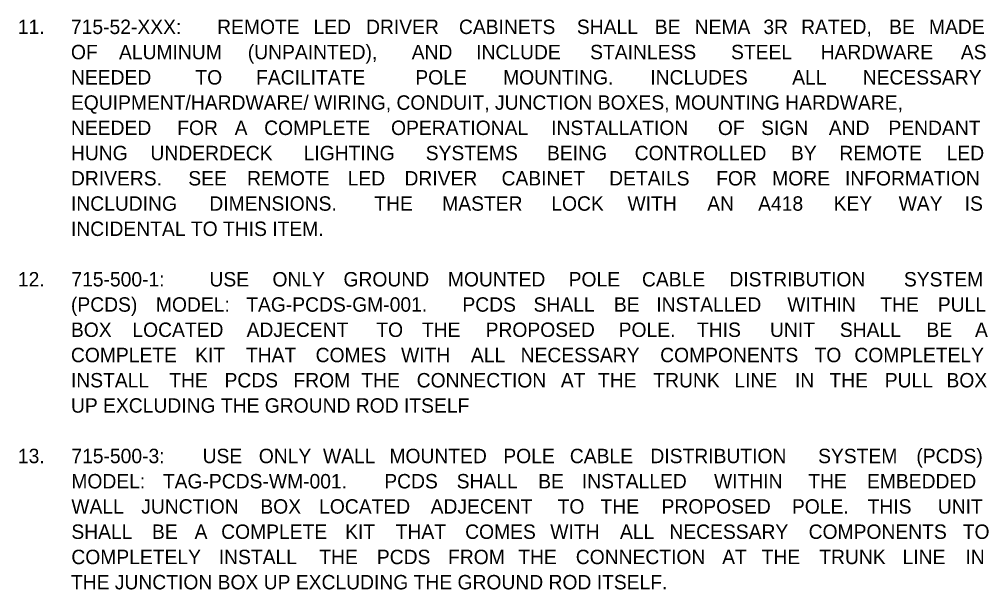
# Model space of a CAD drawing. Extents: x -55 to 2471539, y -90 to 3608906.
# Drawn here: x 543.9 to 1014.7, y 3095.6 to 3372.3 of the extents above; entities that cross this region are included whole.
import ezdxf

# ---------------------------------------------------------------- set-up
doc = ezdxf.new("R2010")
doc.units = 0
doc.layers.add('XSCell', color=7, linetype='Continuous')

msp = doc.modelspace()

# ---------------------------------------------------------------- texts
at = {"layer": 'XSCell'}
for s, p in [('11.', (543.22, 3365.2)), ('715-52-XXX: ', (568.97, 3365.2)), ('REMOTE ', (639.98, 3365.2)), ('LED ', (686.77, 3365.2)), ('DRIVER ', (712.3, 3365.2)), ('CABINETS ', (757.41, 3365.2)), ('SHALL ', (814.68, 3365.2)), ('BE ', (852.51, 3365.2)), ('NEMA ', (871.89, 3365.2)), ('3R ', (905.27, 3365.2)), ('RATED, ', (923.6, 3365.2)), ('BE ', (966.31, 3365.2)), ('MADE ', (985.69, 3365.2)), ('OF ', (568.97, 3352.95)), ('ALUMINUM ', (592.31, 3352.95)), ('(UNPAINTED), ', (654.86, 3352.95)), ('AND ', (734.47, 3352.95)), ('INCLUDE ', (765.76, 3352.95)), ('STAINLESS ', (821.12, 3352.95)), ('STEEL ', (889.55, 3352.95)), ('HARDWARE ', (933.07, 3352.95)), ('AS ', (1001.15, 3352.95)), ('NEEDED ', (568.97, 3340.7)), ('TO ', (629.41, 3340.7)), ('FACILITATE ', (658.89, 3340.7)), ('POLE ', (736.22, 3340.7)), ('MOUNTING. ', (778.86, 3340.7)), ('INCLUDES ', (850.34, 3340.7)), ('ALL ', (919.26, 3340.7)), ('NECESSARY ', (953.5, 3340.7)), ('EQUIPMENT/HARDWARE/ WIRING, CONDUIT, JUNCTION BOXES, MOUNTING HARDWARE, ', (568.97, 3328.45)), ('NEEDED ', (568.97, 3316.2)), ('FOR ', (620.6, 3316.2)), ('A ', (648.48, 3316.2)), ('COMPLETE ', (662.81, 3316.2)), ('OPERATIONAL ', (724.44, 3316.2)), ('INSTALLATION ', (802.19, 3316.2)), ('OF ', (883.17, 3316.2)), ('SIGN ', (904.17, 3316.2)), ('AND ', (937.04, 3316.2)), ('PENDANT ', (966, 3316.2)), ('HUNG ', (568.97, 3303.95)), ('UNDERDECK ', (607.59, 3303.95)), ('LIGHTING ', (681.96, 3303.95)), ('SYSTEMS ', (741.27, 3303.95)), ('BEING ', (800.17, 3303.95)), ('CONTROLLED ', (842.75, 3303.95)), ('BY ', (918.66, 3303.95)), ('REMOTE ', (942.16, 3303.95)), ('LED ', (994.28, 3303.95)), ('DRIVERS. ', (568.97, 3291.7)), ('SEE ', (625.96, 3291.7)), ('REMOTE ', (654.53, 3291.7)), ('LED ', (703.36, 3291.7)), ('DRIVER ', (730.96, 3291.7)), ('CABINET ', (778.11, 3291.7)), ('DETAILS ', (830.37, 3291.7)), ('FOR ', (882.35, 3291.7)), ('MORE ', (909.54, 3291.7)), ('INFORMATION ', (944.87, 3291.7)), ('INCLUDING ', (568.97, 3279.45)), ('DIMENSIONS. ', (636.19, 3279.45)), ('THE ', (716.33, 3279.45)), ('MASTER ', (749.29, 3279.45)), ('LOCK ', (802.27, 3279.45)), ('WITH ', (839.28, 3279.45)), ('AN ', (877.99, 3279.45)), ('A418 ', (902.72, 3279.45)), ('KEY ', (939.37, 3279.45)), ('WAY ', (970.96, 3279.45)), ('IS ', (1003.04, 3279.45)), ('INCIDENTAL TO THIS ITEM.', (568.97, 3267.2)), ('12.', (543.22, 3242.7)), ('715-500-1: ', (569.17, 3242.7)), ('USE ', (636.23, 3242.7)), ('ONLY ', (666.85, 3242.7)), ('GROUND ', (701.34, 3242.7)), ('MOUNTED ', (752.04, 3242.7)), ('POLE ', (810.68, 3242.7)), ('CABLE ', (846.3, 3242.7)), ('DISTRIBUTION ', (888.74, 3242.7)), ('SYSTEM ', (973.52, 3242.7)), ('(PCDS) ', (568.97, 3230.45)), ('MODEL: ', (610.23, 3230.45)), ('TAG-PCDS-GM-001. ', (654.09, 3230.45)), ('PCDS ', (759.09, 3230.45)), ('SHALL ', (793.65, 3230.45)), ('BE ', (832.67, 3230.45)), ('INSTALLED ', (853.25, 3230.45)), ('WITHIN ', (916.87, 3230.45)), ('THE ', (962.03, 3230.45)), ('PULL ', (989.98, 3230.45)), ('BOX ', (568.97, 3218.2)), ('LOCATED ', (598.82, 3218.2)), ('ADJECENT ', (654.29, 3218.2)), ('TO ', (717.27, 3218.2)), ('THE ', (739.4, 3218.2)), ('PROPOSED ', (770.36, 3218.2)), ('POLE. ', (834.98, 3218.2)), ('THIS ', (873.04, 3218.2)), ('UNIT ', (908.47, 3218.2)), ('SHALL ', (942.4, 3218.2)), ('BE ', (984.44, 3218.2)), ('A ', (1008.04, 3218.2)), ('COMPLETE ', (568.97, 3205.95)), ('KIT ', (629.29, 3205.95)), ('THAT ', (653.96, 3205.95)), ('COMES ', (687.81, 3205.95)), ('WITH ', (729.3, 3205.95)), ('ALL ', (763.24, 3205.95)), ('NECESSARY ', (787.36, 3205.95)), ('COMPONENTS ', (855.13, 3205.95)), ('TO ', (930.1, 3205.95)), ('COMPLETELY ', (949.45, 3205.95)), ('INSTALL ', (568.97, 3193.7)), ('THE ', (616.69, 3193.7)), ('PCDS ', (643.55, 3193.7)), ('FROM ', (677.03, 3193.7)), ('THE ', (710.01, 3193.7)), ('CONNECTION ', (736.88, 3193.7)), ('AT ', (806.88, 3193.7)), ('THE ', (824.96, 3193.7)), ('TRUNK ', (851.82, 3193.7)), ('LINE ', (891.16, 3193.7)), ('IN ', (920.6, 3193.7)), ('THE ', (937.35, 3193.7)), ('PULL ', (964.22, 3193.7)), ('BOX ', (994.18, 3193.7)), ('UP EXCLUDING THE GROUND ROD ITSELF', (568.97, 3181.45)), ('13.', (543.22, 3156.95)), ('715-500-3: ', (569.17, 3156.95)), ('USE ', (632.91, 3156.95)), ('ONLY ', (660.21, 3156.95)), ('WALL ', (691.38, 3156.95)), ('MOUNTED ', (723.64, 3156.95)), ('POLE ', (778.96, 3156.95)), ('CABLE ', (811.26, 3156.95)), ('DISTRIBUTION ', (850.39, 3156.95)), ('SYSTEM ', (931.85, 3156.95)), ('(PCDS) ', (979.56, 3156.95)), ('MODEL: ', (569.17, 3144.7)), ('TAG-PCDS-WM-001. ', (613.61, 3144.7)), ('PCDS ', (721.15, 3144.7)), ('SHALL ', (756.3, 3144.7)), ('BE ', (795.91, 3144.7)), ('INSTALLED ', (817.08, 3144.7)), ('WITHIN ', (881.29, 3144.7)), ('THE ', (927.04, 3144.7)), ('EMBEDDED ', (955.58, 3144.7)), ('WALL ', (569.17, 3132.45)), ('JUNCTION ', (603.11, 3132.45)), ('BOX ', (660.95, 3132.45)), ('LOCATED ', (689.5, 3132.45)), ('ADJECENT ', (743.66, 3132.45)), ('TO ', (805.34, 3132.45)), ('THE ', (826.16, 3132.45)), ('PROPOSED ', (855.81, 3132.45)), ('POLE. ', (919.13, 3132.45)), ('THIS ', (955.87, 3132.45)), ('UNIT ', (990, 3132.45)), ('SHALL ', (569.17, 3120.2)), ('BE ', (608.32, 3120.2)), ('A ', (629.02, 3120.2)), ('COMPLETE ', (641.93, 3120.2)), ('KIT ', (702.14, 3120.2)), ('THAT ', (726.69, 3120.2)), ('COMES ', (760.42, 3120.2)), ('WITH ', (801.78, 3120.2)), ('ALL ', (835.61, 3120.2)), ('NECESSARY ', (859.61, 3120.2)), ('COMPONENTS ', (927.25, 3120.2)), ('TO ', (1002.1, 3120.2)), ('COMPLETELY ', (569.17, 3107.95)), ('INSTALL ', (640.75, 3107.95)), ('THE ', (689.57, 3107.95)), ('PCDS ', (717.54, 3107.95)), ('FROM ', (752.12, 3107.95)), ('THE ', (786.19, 3107.95)), ('CONNECTION ', (814.16, 3107.95)), ('AT ', (885.26, 3107.95)), ('THE ', (904.44, 3107.95)), ('TRUNK ', (932.41, 3107.95)), ('LINE ', (972.85, 3107.95)), ('IN ', (1003.39, 3107.95)), ('THE JUNCTION BOX UP EXCLUDING THE GROUND ROD ITSELF. ', (568.97, 3095.7))]:
    msp.add_text(s, height=7, dxfattribs=at).set_placement(p)

doc.saveas('drawing.dxf')
